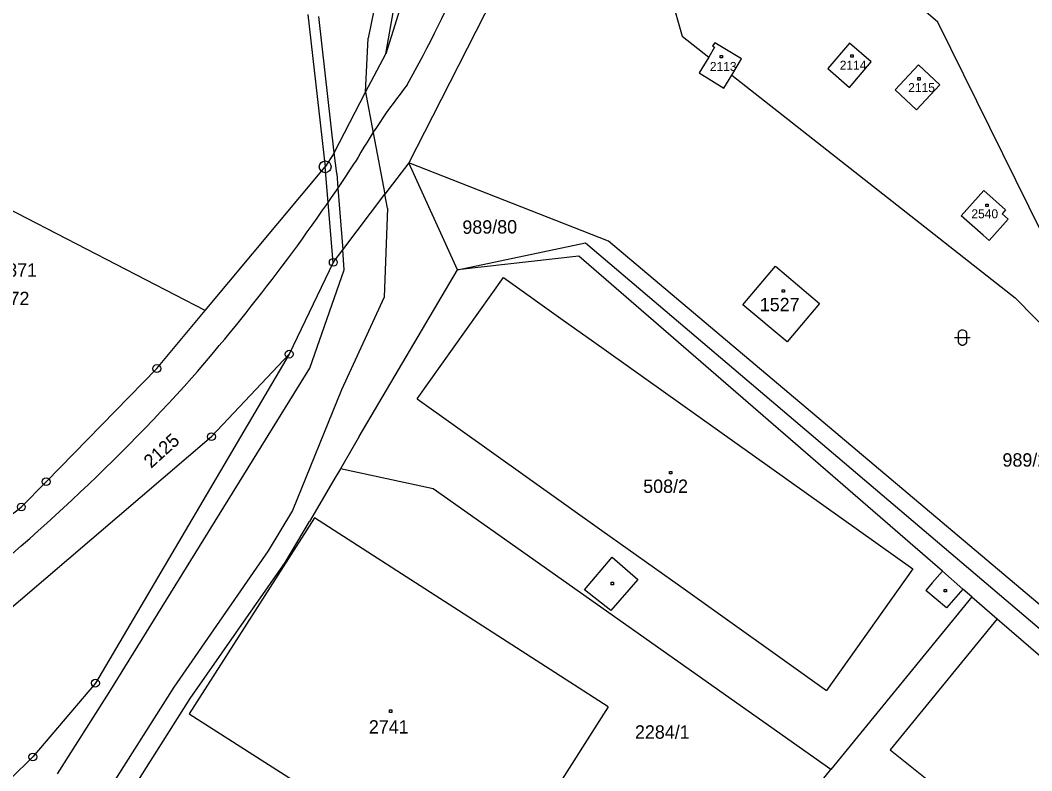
# Model space of a CAD drawing. Extents: x -795483 to -789093, y -1112258 to -1108741.
# Drawn here: x -791985.8 to -791857.2, y -1109684.3 to -1109588.9 of the extents above; entities that cross this region are included whole.
import ezdxf

# ---------------------------------------------------------------- set-up
doc = ezdxf.new("R2010")
doc.units = 0
for name, color, linetype in [('Vrstva 1', 7, 'Continuous'), ('Vrstva 10', 7, 'Continuous'), ('Vrstva 14', 7, 'Continuous'), ('Vrstva 15', 7, 'Continuous'), ('Vrstva 16', 7, 'Continuous'), ('Vrstva 2', 7, 'Continuous'), ('Vrstva 23', 7, 'Continuous'), ('Vrstva 25', 7, 'Continuous'), ('Vrstva 28', 7, 'Continuous')]:
    doc.layers.add(name, color=color, linetype=linetype)

msp = doc.modelspace()

# ---------------------------------------------------------------- linework, layer by layer
at = {"layer": 'Vrstva 1'}
for p, q in [((-791913.01, -1109551.17), (-791901.65, -1109590.96)), ((-791869.18, -1109589.15), (-791913.01, -1109551.17)), ((-791939.32, -1109593.19), (-791933.39, -1109560.42)), ((-791917.89, -1109570.79), (-791933.38, -1109601.14)), ((-791933.45, -1109574.5), (-791939.32, -1109593.19)), ((-791949.21, -1109588.2), (-791947.01, -1109607.55)), ((-791853.19, -1109621.6), (-791869.18, -1109589.15)), ((-791901.65, -1109590.96), (-791898.28, -1109593.6)), ((-791897.53, -1109592.35), (-791898.28, -1109593.6)), ((-791897.49, -1109591.79), (-791897.79, -1109592.19)), ((-791897.79, -1109592.19), (-791897.53, -1109592.35)), ((-791894.1, -1109593.84), (-791897.49, -1109591.79)), ((-791880.39, -1109591.84), (-791883.14, -1109595.06)), ((-791877.62, -1109594.22), (-791880.39, -1109591.84)), ((-791941.9, -1109598.05), (-791939.32, -1109593.19)), ((-791898.28, -1109593.6), (-791899.5, -1109595.62)), ((-791895.35, -1109595.9), (-791894.1, -1109593.84)), ((-791880.37, -1109597.49), (-791877.62, -1109594.22)), ((-791874.6, -1109597.77), (-791871.64, -1109594.58)), ((-791871.64, -1109594.58), (-791868.91, -1109597.12)), ((-791962.26, -1109625.83), (-792019.39, -1109596.27)), ((-791899.5, -1109595.62), (-791896.34, -1109597.55)), ((-791896.34, -1109597.55), (-791895.35, -1109595.9)), ((-791895.35, -1109595.9), (-791859.32, -1109624.2)), ((-791883.14, -1109595.06), (-791880.37, -1109597.49)), ((-791868.91, -1109597.12), (-791871.86, -1109600.29)), ((-791945.88, -1109605.78), (-791941.9, -1109598.05)), ((-791871.86, -1109600.29), (-791874.6, -1109597.77)), ((-791933.38, -1109601.14), (-791936.4, -1109607.05)), ((-791945.88, -1109605.78), (-791947.01, -1109607.55)), ((-791962.26, -1109625.83), (-791947.01, -1109607.55)), ((-791945.98, -1109619.69), (-791947.01, -1109607.55)), ((-791936.4, -1109607.05), (-791939.42, -1109611.04)), ((-791930.18, -1109620.63), (-791936.4, -1109607.05)), ((-791911, -1109616.98), (-791936.4, -1109607.05)), ((-791944.78, -1109618.11), (-791939.42, -1109611.04)), ((-791866.18, -1109613.77), (-791863.33, -1109610.57)), ((-791863.33, -1109610.57), (-791860.57, -1109613.03)), ((-791863.4, -1109616.23), (-791866.18, -1109613.77)), ((-791860.25, -1109614.19), (-791862.64, -1109616.9)), ((-791860.57, -1109613.03), (-791861, -1109613.52)), ((-791861, -1109613.52), (-791860.25, -1109614.19)), ((-791862.64, -1109616.9), (-791863.4, -1109616.23)), ((-791945.98, -1109619.69), (-791944.78, -1109618.11)), ((-791930.18, -1109620.63), (-791913.92, -1109617.19)), ((-791913.92, -1109617.19), (-791837.48, -1109682.19)), ((-791847.86, -1109670.26), (-791911, -1109616.98)), ((-791914.76, -1109618.89), (-791930.18, -1109620.63)), ((-791868.59, -1109658.92), (-791914.76, -1109618.89)), ((-791945.98, -1109619.69), (-791951.58, -1109631.36)), ((-791942.67, -1109641.84), (-791930.18, -1109620.63)), ((-791893.93, -1109625.09), (-791889.81, -1109620.18)), ((-791889.81, -1109620.18), (-791884.18, -1109624.9)), ((-791859.32, -1109624.2), (-791838.65, -1109645.44)), ((-791968.4, -1109633.19), (-791962.26, -1109625.83)), ((-791888.29, -1109629.81), (-791893.93, -1109625.09)), ((-791884.18, -1109624.9), (-791888.29, -1109629.81)), ((-791951.58, -1109631.36), (-791976.2, -1109673.16)), ((-791961.46, -1109641.84), (-791951.58, -1109631.36)), ((-791968.4, -1109633.19), (-791982.46, -1109647.56)), ((-792002.49, -1109676.88), (-791961.46, -1109641.84)), ((-791942.67, -1109641.84), (-791945.08, -1109645.94)), ((-791945.08, -1109645.94), (-791945.89, -1109647.32)), ((-791933.29, -1109648.46), (-791945.08, -1109645.94)), ((-791985.62, -1109650.78), (-791982.46, -1109647.56)), ((-791945.89, -1109647.32), (-791949.02, -1109652.63)), ((-791882.76, -1109684.15), (-791933.29, -1109648.46)), ((-792022.82, -1109679.59), (-791985.62, -1109650.78)), ((-791948.37, -1109652.16), (-791964.28, -1109677.07)), ((-791952.08, -1109657.83), (-791949.02, -1109652.63)), ((-791911.04, -1109676.18), (-791948.37, -1109652.16)), ((-791964.15, -1109675.11), (-791952.08, -1109657.83)), ((-791865.97, -1109661.2), (-791868.59, -1109658.92)), ((-791864.85, -1109662.19), (-791865.97, -1109661.2)), ((-791864.85, -1109662.19), (-791882.76, -1109684.15)), ((-791864.85, -1109662.19), (-791861.64, -1109664.97)), ((-791861.64, -1109664.97), (-791875.21, -1109681.64)), ((-791861.64, -1109664.97), (-791831.46, -1109691.13)), ((-791976.2, -1109673.16), (-791984.15, -1109682.54)), ((-791974.78, -1109691.82), (-791964.15, -1109675.11)), ((-791964.28, -1109677.07), (-791951.17, -1109685.45)), ((-791911.04, -1109676.18), (-791927.63, -1109702.08)), ((-791875.21, -1109681.64), (-791867.24, -1109688)), ((-791984.15, -1109682.54), (-791987, -1109685.32)), ((-791889.58, -1109692.5), (-791882.76, -1109684.15))]:
    msp.add_line(p, q, dxfattribs=at)
at = {"layer": 'Vrstva 10'}
for centre, radius, start, end in [((-792145.24, -1109483.09), 237.8, 331.3395, 339.5094), ((-791875.72, -1109645.27), 77.6, 141.6621, 150.4214), ((-792151.83, -1109470.53), 249.28, 318.9104, 326.8164), ((-792153.51, -1109463.63), 255.12, 307.5682, 317.989)]:
    msp.add_arc(centre, radius, start, end, dxfattribs=at)
at = {"layer": 'Vrstva 2'}
for p, q in [((-791935.86, -1109563.1), (-791941.55, -1109591.2)), ((-791945.88, -1109605.78), (-791947.8, -1109588.47)), ((-791941.9, -1109598.05), (-791941.55, -1109591.2)), ((-791941.9, -1109598.05), (-791940.91, -1109603.25)), ((-791940.91, -1109603.25), (-791939.42, -1109611.04)), ((-791945.53, -1109608.4), (-791945.88, -1109605.78)), ((-791945.53, -1109608.4), (-791945.39, -1109610.25)), ((-791945.39, -1109610.25), (-791944.78, -1109618.11)), ((-791939.08, -1109612.82), (-791939.42, -1109611.04)), ((-791939.08, -1109612.82), (-791939.53, -1109624.11)), ((-791944.59, -1109620.64), (-791944.78, -1109618.11)), ((-791948.95, -1109633.15), (-791944.59, -1109620.64)), ((-791935.33, -1109637.05), (-791924.36, -1109621.63)), ((-791924.36, -1109621.63), (-791916.48, -1109627.24)), ((-791939.53, -1109624.11), (-791944.94, -1109635.91)), ((-791916.48, -1109627.24), (-791913.19, -1109629.58)), ((-791913.19, -1109629.58), (-791872.34, -1109658.65)), ((-791974.45, -1109674.36), (-791948.95, -1109633.15)), ((-791944.94, -1109635.91), (-791951.18, -1109651.24)), ((-791935.33, -1109637.05), (-791911.87, -1109653.75)), ((-791951.18, -1109651.24), (-791954.25, -1109656.35)), ((-791911.87, -1109653.75), (-791901.83, -1109660.89)), ((-791954.25, -1109656.35), (-791966.24, -1109673.68)), ((-791914.04, -1109661.31), (-791910.55, -1109657.15)), ((-791910.55, -1109657.15), (-791907.3, -1109659.97)), ((-791872.34, -1109658.65), (-791883.31, -1109674.08)), ((-791869.88, -1109660.4), (-791868.59, -1109658.92)), ((-791907.3, -1109659.97), (-791910.71, -1109663.91)), ((-791869.88, -1109660.4), (-791870.69, -1109661.37)), ((-791910.71, -1109663.91), (-791914.04, -1109661.31)), ((-791901.83, -1109660.89), (-791883.31, -1109674.08)), ((-791868.07, -1109663.61), (-791870.69, -1109661.37)), ((-791865.97, -1109661.2), (-791868.07, -1109663.61)), ((-791981.02, -1109684.68), (-791974.45, -1109674.36)), ((-791966.24, -1109673.68), (-791976.88, -1109690.38))]:
    msp.add_line(p, q, dxfattribs=at)
at = {"layer": 'Vrstva 23'}
for p, q in [((-791866.44, -1109628.45), (-791866.34, -1109628.35)), ((-791866.34, -1109628.35), (-791866.14, -1109628.25)), ((-791866.14, -1109628.25), (-791865.94, -1109628.25)), ((-791865.94, -1109628.25), (-791865.74, -1109628.35)), ((-791865.74, -1109628.35), (-791865.64, -1109628.45)), ((-791867.04, -1109629.25), (-791865.04, -1109629.25)), ((-791866.54, -1109628.65), (-791866.44, -1109628.45)), ((-791866.54, -1109629.85), (-791866.54, -1109628.65)), ((-791865.64, -1109628.45), (-791865.54, -1109628.65)), ((-791865.54, -1109628.65), (-791865.54, -1109629.85)), ((-791866.44, -1109630.05), (-791866.54, -1109629.85)), ((-791866.34, -1109630.15), (-791866.44, -1109630.05)), ((-791866.14, -1109630.25), (-791866.34, -1109630.15)), ((-791865.94, -1109630.25), (-791866.14, -1109630.25)), ((-791865.74, -1109630.15), (-791865.94, -1109630.25)), ((-791865.64, -1109630.05), (-791865.74, -1109630.15)), ((-791865.54, -1109629.85), (-791865.64, -1109630.05))]:
    msp.add_line(p, q, dxfattribs=at)
at = {"layer": 'Vrstva 25'}
for p, q in [((-791896.83, -1109593.41), (-791896.53, -1109593.41)), ((-791896.83, -1109593.71), (-791896.83, -1109593.41)), ((-791896.53, -1109593.71), (-791896.83, -1109593.71)), ((-791896.53, -1109593.41), (-791896.53, -1109593.71)), ((-791880.24, -1109593.33), (-791879.94, -1109593.33)), ((-791880.24, -1109593.63), (-791880.24, -1109593.33)), ((-791879.94, -1109593.63), (-791880.24, -1109593.63)), ((-791879.94, -1109593.33), (-791879.94, -1109593.63)), ((-791871.72, -1109596.22), (-791871.42, -1109596.22)), ((-791871.72, -1109596.52), (-791871.72, -1109596.22)), ((-791871.42, -1109596.22), (-791871.42, -1109596.52)), ((-791871.42, -1109596.52), (-791871.72, -1109596.52)), ((-791863.06, -1109612.31), (-791862.76, -1109612.31)), ((-791863.06, -1109612.61), (-791863.06, -1109612.31)), ((-791862.76, -1109612.61), (-791863.06, -1109612.61)), ((-791862.76, -1109612.31), (-791862.76, -1109612.61)), ((-791888.93, -1109623.17), (-791888.63, -1109623.17)), ((-791888.93, -1109623.47), (-791888.93, -1109623.17)), ((-791888.63, -1109623.17), (-791888.63, -1109623.47)), ((-791888.63, -1109623.47), (-791888.93, -1109623.47)), ((-791903.27, -1109646.26), (-791902.97, -1109646.26)), ((-791903.27, -1109646.56), (-791903.27, -1109646.26)), ((-791902.97, -1109646.26), (-791902.97, -1109646.56)), ((-791902.97, -1109646.56), (-791903.27, -1109646.56)), ((-791910.67, -1109660.35), (-791910.37, -1109660.35)), ((-791910.67, -1109660.65), (-791910.67, -1109660.35)), ((-791910.37, -1109660.35), (-791910.37, -1109660.65)), ((-791910.37, -1109660.65), (-791910.67, -1109660.65)), ((-791868.37, -1109661.26), (-791868.07, -1109661.26)), ((-791868.37, -1109661.56), (-791868.37, -1109661.26)), ((-791868.07, -1109661.56), (-791868.37, -1109661.56)), ((-791868.07, -1109661.26), (-791868.07, -1109661.56)), ((-791938.84, -1109676.57), (-791938.54, -1109676.57)), ((-791938.84, -1109676.87), (-791938.84, -1109676.57)), ((-791938.54, -1109676.87), (-791938.84, -1109676.87)), ((-791938.54, -1109676.57), (-791938.54, -1109676.87))]:
    msp.add_line(p, q, dxfattribs=at)
at = {"layer": 'Vrstva 28'}
for centre, radius in [((-791947.01, -1109607.55), 0.75), ((-791947.01, -1109607.55), 0.01), ((-791945.98, -1109619.69), 0.5), ((-791945.98, -1109619.69), 0.01), ((-791951.58, -1109631.36), 0.5), ((-791951.58, -1109631.36), 0.01), ((-791968.4, -1109633.19), 0.5), ((-791968.4, -1109633.19), 0.01), ((-791961.46, -1109641.84), 0.5), ((-791961.46, -1109641.84), 0.01), ((-791982.46, -1109647.56), 0.5), ((-791982.46, -1109647.56), 0.01), ((-791985.62, -1109650.78), 0.5), ((-791985.62, -1109650.78), 0.01), ((-791976.2, -1109673.16), 0.5), ((-791976.2, -1109673.16), 0.01), ((-791984.15, -1109682.54), 0.5), ((-791984.15, -1109682.54), 0.01)]:
    msp.add_circle(centre, radius, dxfattribs=at)

# ---------------------------------------------------------------- texts
at = {"layer": 'Vrstva 14'}
for s, rotation, p in [('989/80', 0.469, (-791929.57, -1109616.07)), ('2125', 42.0722, (-791969.12, -1109645.93))]:
    msp.add_text(s, height=1.7, rotation=rotation, dxfattribs=at).set_placement(p)
for s, p in [('989/20', (-791860.95, -1109645.65)), ('2284/1', (-791907.65, -1109680.22))]:
    msp.add_text(s, height=1.7, dxfattribs=at).set_placement(p)
at = {"layer": 'Vrstva 15'}
for s, height, p in [('2113', 1.14, (-791898.13, -1109595.37)), ('2114', 1.14, (-791881.63, -1109595.21)), ('2115', 1.14, (-791872.93, -1109598.06)), ('2540', 1.14, (-791864.9, -1109614.09)), ('1527', 1.7, (-791891.79, -1109625.9)), ('508/2', 1.7, (-791906.6, -1109648.99)), ('2741', 1.7, (-791941.46, -1109679.57))]:
    msp.add_text(s, height=height, dxfattribs=at).set_placement(p)
at = {"layer": 'Vrstva 16'}
for s, p in [('1871', (-791988.68, -1109621.52)), ('1872', (-791989.65, -1109625.13))]:
    msp.add_text(s, height=1.7, dxfattribs=at).set_placement(p)

doc.saveas('drawing.dxf')
